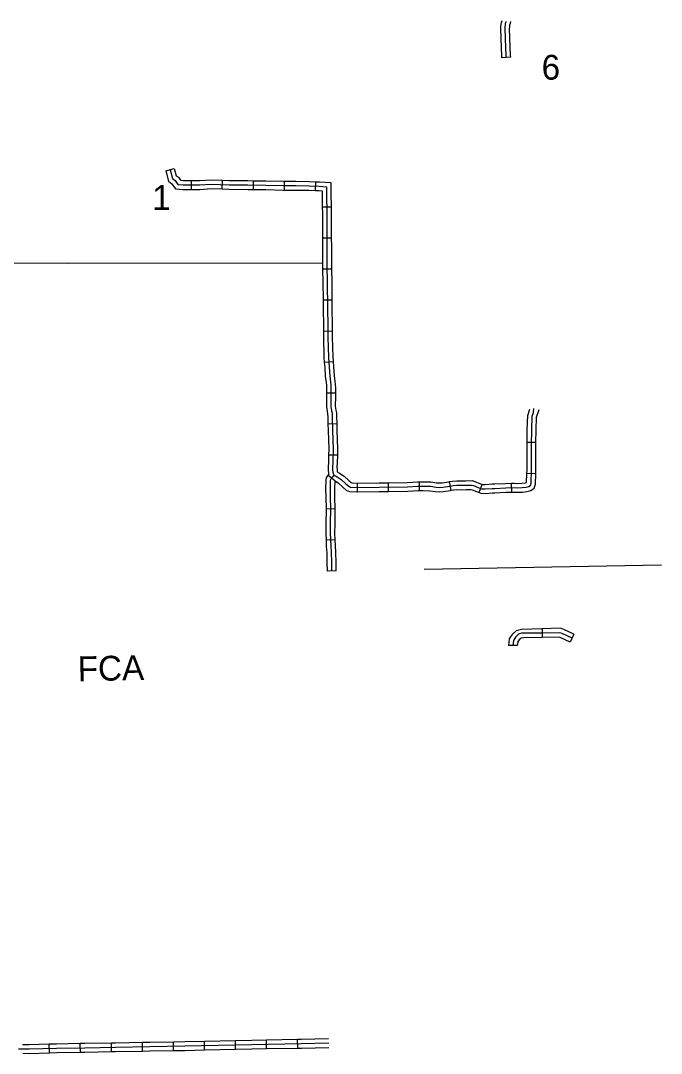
# Model space of a CAD drawing. Extents: x 1127717 to 1741049, y 2026793 to 2244711.
# Drawn here: x 1524221 to 1535120, y 2197760 to 2215332 of the extents above; entities that cross this region are included whole.
import ezdxf

# ---------------------------------------------------------------- set-up
doc = ezdxf.new("R2010")
doc.units = 0
for name, color, linetype in [('26', 7, 'Continuous'), ('32', 7, 'Continuous'), ('5', 7, 'Continuous')]:
    doc.layers.add(name, color=color, linetype=linetype)

msp = doc.modelspace()

# ---------------------------------------------------------------- linework, layer by layer
at = {"layer": '32'}
for p, q in [((1532558, 2214709), (1532408, 2214697)), ((1526689, 2212777), (1526834, 2212815)), ((1527126, 2212461), (1527126, 2212611)), ((1527651, 2212468), (1527656, 2212618)), ((1528181, 2212459), (1528183, 2212609)), ((1528710, 2212450), (1528710, 2212600)), ((1529235, 2212442), (1529240, 2212592)), ((1529352, 2212164), (1529502, 2212166)), ((1529356, 2211636), (1529506, 2211637)), ((1529358, 2211107), (1529508, 2211110)), ((1529366, 2210580), (1529516, 2210581)), ((1529373, 2210054), (1529523, 2210051)), ((1529387, 2209520), (1529537, 2209531)), ((1529425, 2208999), (1529575, 2208999)), ((1529448, 2208471), (1529598, 2208475)), ((1532987, 2208152), (1532837, 2208154)), ((1529460, 2207946), (1529610, 2207944)), ((1529568, 2207500), (1529451, 2207593)), ((1531007, 2207337), (1531007, 2207487)), ((1531547, 2207341), (1531516, 2207488)), ((1532983, 2207623), (1532833, 2207627)), ((1529953, 2207312), (1529950, 2207462)), ((1530480, 2207320), (1530479, 2207470)), ((1532022, 2207301), (1532073, 2207442)), ((1532575, 2207310), (1532573, 2207460)), ((1529572, 2207025), (1529422, 2207022)), ((1529572, 2206498), (1529422, 2206492)), ((1529589, 2205968), (1529439, 2205967)), ((1533091, 2204985), (1533094, 2204835)), ((1533632, 2204893), (1533570, 2204757)), ((1528934, 2197850), (1528931, 2198000)), ((1524712, 2197771), (1524707, 2197921)), ((1525238, 2197781), (1525236, 2197931)), ((1525766, 2197790), (1525764, 2197940)), ((1526294, 2197799), (1526292, 2197949)), ((1526822, 2197808), (1526820, 2197958)), ((1527350, 2197819), (1527347, 2197969)), ((1527878, 2197831), (1527875, 2197981)), ((1528406, 2197841), (1528403, 2197991))]:
    msp.add_line(p, q, dxfattribs=at)
for points in [[(1532408, 2214697), (1532405, 2214735), (1532399, 2214868), (1532393, 2215033), (1532389, 2215201), (1532391, 2215233)], [(1532391, 2215233), (1532400, 2215300), (1532412, 2215332)], [(1532483, 2214703), (1532480, 2214740), (1532474, 2214871), (1532468, 2215035), (1532464, 2215200), (1532468, 2215290), (1532486, 2215325)], [(1532558, 2214709), (1532555, 2214745), (1532549, 2214874), (1532543, 2215038), (1532539, 2215200), (1532540, 2215228)], [(1532540, 2215228), (1532544, 2215258), (1532552, 2215290), (1532561, 2215319)], [(1526689, 2212777), (1526737, 2212599), (1526795, 2212558), (1526854, 2212471), (1526981, 2212461), (1527126, 2212461)], [(1526762, 2212796), (1526802, 2212645), (1526849, 2212612), (1526896, 2212543), (1526984, 2212536), (1527264, 2212536), (1527464, 2212550), (1527766, 2212539), (1528086, 2212536), (1528392, 2212532), (1528690, 2212525), (1528894, 2212525), (1529127, 2212521), (1529298, 2212515), (1529423, 2212507)], [(1526834, 2212815), (1526867, 2212691), (1526904, 2212666), (1526938, 2212615), (1526987, 2212611), (1527126, 2212611)], [(1527126, 2212611), (1527261, 2212611), (1527463, 2212625), (1527656, 2212618)], [(1527656, 2212618), (1527768, 2212614), (1528087, 2212611), (1528183, 2212609)], [(1528183, 2212609), (1528393, 2212607), (1528691, 2212600), (1528710, 2212600)], [(1528710, 2212600), (1528894, 2212600), (1529129, 2212596), (1529240, 2212592)], [(1529240, 2212592), (1529302, 2212590), (1529498, 2212577), (1529499, 2212387), (1529502, 2212166)], [(1527126, 2212461), (1527267, 2212461), (1527465, 2212475), (1527651, 2212468)], [(1527651, 2212468), (1527764, 2212464), (1528086, 2212461), (1528181, 2212459)], [(1528181, 2212459), (1528391, 2212457), (1528690, 2212450), (1528710, 2212450)], [(1528710, 2212450), (1528893, 2212450), (1529125, 2212446), (1529235, 2212442)], [(1529235, 2212442), (1529295, 2212440), (1529349, 2212436), (1529349, 2212385), (1529352, 2212164)], [(1529423, 2212507), (1529424, 2212386), (1529428, 2212053), (1529430, 2211805), (1529432, 2211490), (1529432, 2211332), (1529432, 2211155), (1529438, 2210878), (1529442, 2210442), (1529448, 2210136), (1529448, 2210056), (1529446, 2209945), (1529456, 2209602), (1529468, 2209437), (1529478, 2209288), (1529492, 2209183), (1529498, 2209139), (1529500, 2209078), (1529500, 2208936), (1529498, 2208769), (1529510, 2208693), (1529518, 2208652), (1529520, 2208591), (1529526, 2208362), (1529536, 2208039), (1529532, 2207812), (1529526, 2207737), (1529528, 2207687), (1529532, 2207649), (1529551, 2207591)], [(1529352, 2212164), (1529353, 2212052), (1529355, 2211805), (1529356, 2211636)], [(1529502, 2212166), (1529503, 2212053), (1529505, 2211806), (1529506, 2211637)], [(1529356, 2211636), (1529357, 2211490), (1529357, 2211332), (1529357, 2211154), (1529358, 2211107)], [(1529506, 2211637), (1529507, 2211490), (1529507, 2211332), (1529507, 2211156), (1529508, 2211110)], [(1529358, 2211107), (1529363, 2210877), (1529366, 2210580)], [(1529508, 2211110), (1529513, 2210879), (1529516, 2210581)], [(1529366, 2210580), (1529367, 2210440), (1529373, 2210135), (1529373, 2210056), (1529373, 2210054)], [(1529516, 2210581), (1529517, 2210443), (1529523, 2210137), (1529523, 2210055), (1529523, 2210051)], [(1529373, 2210054), (1529371, 2209945), (1529381, 2209598), (1529387, 2209520)], [(1529523, 2210051), (1529521, 2209946), (1529531, 2209606), (1529537, 2209531)], [(1529387, 2209520), (1529393, 2209432), (1529404, 2209281), (1529418, 2209173), (1529424, 2209132), (1529425, 2209077), (1529425, 2208999)], [(1529537, 2209531), (1529543, 2209442), (1529553, 2209296), (1529567, 2209193), (1529573, 2209145), (1529575, 2209080), (1529575, 2208999)], [(1529425, 2208999), (1529425, 2208936), (1529423, 2208764), (1529437, 2208680), (1529443, 2208643), (1529445, 2208589), (1529448, 2208471)], [(1529575, 2208999), (1529575, 2208935), (1529573, 2208774), (1529584, 2208705), (1529593, 2208660), (1529595, 2208593), (1529598, 2208475)], [(1529514, 2205968), (1529513, 2206111), (1529509, 2206280), (1529501, 2206397), (1529492, 2206611), (1529494, 2206772), (1529497, 2207023), (1529492, 2207225), (1529490, 2207364), (1529494, 2207506), (1529497, 2207530), (1529512, 2207550), (1529533, 2207570), (1529551, 2207591), (1529576, 2207586), (1529608, 2207569), (1529675, 2207522), (1529754, 2207449), (1529801, 2207409), (1529834, 2207394), (1529942, 2207387), (1530320, 2207394), (1530799, 2207399), (1530978, 2207412), (1531063, 2207412), (1531191, 2207409), (1531289, 2207394), (1531345, 2207390), (1531401, 2207394), (1531520, 2207412), (1531578, 2207424), (1531640, 2207428), (1531718, 2207426), (1531796, 2207428), (1531891, 2207430), (1531925, 2207420), (1532004, 2207387), (1532063, 2207366), (1532125, 2207363), (1532243, 2207374), (1532289, 2207373), (1532472, 2207384), (1532615, 2207386), (1532679, 2207384), (1532752, 2207386), (1532820, 2207394), (1532866, 2207406), (1532892, 2207425), (1532903, 2207460), (1532910, 2207687), (1532911, 2208013), (1532911, 2208113), (1532915, 2208371), (1532921, 2208600), (1532944, 2208667), (1532949, 2208731)], [(1532837, 2208154), (1532840, 2208372), (1532847, 2208614), (1532883, 2208721)], [(1532987, 2208152), (1532990, 2208369), (1532996, 2208587), (1533041, 2208718)], [(1529448, 2208471), (1529451, 2208360), (1529461, 2208038), (1529460, 2207946)], [(1529598, 2208475), (1529601, 2208364), (1529611, 2208039), (1529610, 2207944)], [(1532833, 2207627), (1532835, 2207689), (1532836, 2208014), (1532836, 2208114), (1532837, 2208154)], [(1532983, 2207623), (1532985, 2207686), (1532986, 2208013), (1532986, 2208113), (1532987, 2208152)], [(1529460, 2207946), (1529457, 2207815), (1529451, 2207739), (1529453, 2207682), (1529458, 2207633), (1529465, 2207612)], [(1529610, 2207944), (1529607, 2207808), (1529601, 2207736), (1529603, 2207693), (1529607, 2207654)], [(1529422, 2207022), (1529417, 2207224), (1529415, 2207364), (1529419, 2207512), (1529425, 2207561), (1529465, 2207612)], [(1529572, 2207025), (1529567, 2207226), (1529565, 2207363), (1529569, 2207500), (1529569, 2207500), (1529568, 2207500)], [(1529568, 2207500), (1529572, 2207503), (1529628, 2207464), (1529704, 2207393), (1529760, 2207345), (1529816, 2207321), (1529941, 2207312), (1529953, 2207312)], [(1529607, 2207654), (1529647, 2207633), (1529723, 2207581), (1529804, 2207505), (1529841, 2207473), (1529853, 2207468), (1529944, 2207462), (1529950, 2207462)], [(1530479, 2207470), (1530795, 2207474), (1530975, 2207487), (1531007, 2207487)], [(1531007, 2207487), (1531064, 2207487), (1531198, 2207484), (1531297, 2207468), (1531344, 2207465), (1531392, 2207469), (1531507, 2207486), (1531516, 2207488)], [(1531516, 2207488), (1531568, 2207498), (1531639, 2207503), (1531718, 2207501), (1531794, 2207503), (1531901, 2207505), (1531950, 2207491), (1532031, 2207457), (1532073, 2207442)], [(1532573, 2207460), (1532615, 2207461), (1532679, 2207459), (1532747, 2207461), (1532806, 2207468), (1532829, 2207474), (1532833, 2207627)], [(1532575, 2207310), (1532614, 2207311), (1532679, 2207309), (1532758, 2207311), (1532833, 2207320), (1532898, 2207336), (1532955, 2207379), (1532978, 2207446), (1532983, 2207623)], [(1529950, 2207462), (1530319, 2207469), (1530479, 2207470)], [(1529953, 2207312), (1530321, 2207319), (1530480, 2207320)], [(1530480, 2207320), (1530802, 2207324), (1530981, 2207337), (1531007, 2207337)], [(1531007, 2207337), (1531062, 2207337), (1531184, 2207334), (1531280, 2207319), (1531346, 2207314), (1531409, 2207320), (1531533, 2207338), (1531547, 2207341)], [(1531547, 2207341), (1531589, 2207349), (1531641, 2207353), (1531719, 2207351), (1531798, 2207353), (1531881, 2207355), (1531900, 2207349), (1531977, 2207318), (1532022, 2207301)], [(1532073, 2207442), (1532078, 2207441), (1532123, 2207438), (1532241, 2207450), (1532288, 2207448), (1532470, 2207459), (1532573, 2207460)], [(1532022, 2207301), (1532048, 2207292), (1532127, 2207288), (1532245, 2207299), (1532290, 2207298), (1532475, 2207309), (1532575, 2207310)], [(1529422, 2206492), (1529417, 2206610), (1529419, 2206773), (1529422, 2207022), (1529422, 2207021)], [(1529572, 2206498), (1529567, 2206612), (1529569, 2206771), (1529572, 2207023), (1529572, 2207025)], [(1529439, 2205967), (1529438, 2206109), (1529434, 2206277), (1529426, 2206393), (1529422, 2206492)], [(1529589, 2205968), (1529588, 2206112), (1529584, 2206284), (1529576, 2206401), (1529572, 2206498)], [(1533091, 2204985), (1533089, 2204985), (1532740, 2204970), (1532648, 2204951), (1532582, 2204887), (1532551, 2204844)], [(1533601, 2204825), (1533431, 2204903), (1533392, 2204918), (1533090, 2204910), (1532742, 2204910), (1532688, 2204895), (1532641, 2204841), (1532603, 2204787), (1532594, 2204699)], [(1533632, 2204893), (1533460, 2204972), (1533405, 2204993), (1533091, 2204985)], [(1532551, 2204844), (1532530, 2204814), (1532519, 2204698)], [(1532676, 2204759), (1532670, 2204700), (1532519, 2204698)], [(1533094, 2204835), (1533091, 2204835), (1532777, 2204832), (1532736, 2204823), (1532701, 2204794), (1532674, 2204757)], [(1533570, 2204757), (1533401, 2204834), (1533378, 2204843), (1533094, 2204835)], [(1528403, 2197991), (1528931, 2198000)], [(1528931, 2198000), (1528993, 2198001), (1529459, 2198012)], [(1529459, 2198012), (1529460, 2198012)], [(1524182, 2197837), (1524207, 2197839), (1524367, 2197836), (1524833, 2197850), (1525313, 2197857), (1525834, 2197866), (1526419, 2197876), (1527016, 2197886), (1528153, 2197912), (1528995, 2197926), (1529461, 2197937)], [(1524254, 2197913), (1524367, 2197911), (1524707, 2197921)], [(1524707, 2197921), (1524832, 2197925), (1525236, 2197931)], [(1525236, 2197931), (1525312, 2197932), (1525764, 2197940)], [(1525764, 2197940), (1525833, 2197941), (1526292, 2197949)], [(1526292, 2197949), (1526418, 2197951), (1526820, 2197958)], [(1526820, 2197958), (1527014, 2197961), (1527347, 2197969)], [(1527347, 2197969), (1527875, 2197981)], [(1527350, 2197819), (1527878, 2197831)], [(1527875, 2197981), (1528152, 2197987), (1528403, 2197991)], [(1527878, 2197831), (1528155, 2197837), (1528406, 2197841)], [(1528406, 2197841), (1528934, 2197850)], [(1528934, 2197850), (1528996, 2197851), (1529462, 2197862)], [(1529462, 2197862), (1529463, 2197862)], [(1524259, 2197763), (1524367, 2197760), (1524712, 2197771)], [(1524712, 2197771), (1524835, 2197775), (1525238, 2197781)], [(1525238, 2197781), (1525314, 2197782), (1525766, 2197790)], [(1525766, 2197790), (1525836, 2197792), (1526294, 2197799)], [(1526294, 2197799), (1526421, 2197801), (1526822, 2197808)], [(1526822, 2197808), (1527017, 2197811), (1527350, 2197819)]]:
    msp.add_lwpolyline(points, dxfattribs=at)
at = {"layer": '5'}
for points in [[(1529357, 2211208), (1525021, 2211198), (1524110, 2211206)], [(1531084, 2205997), (1535120, 2206072)]]:
    msp.add_lwpolyline(points, dxfattribs=at)

# ---------------------------------------------------------------- texts
at = {"layer": '26'}
msp.add_text('FCA', height=422.4, rotation=1.2628, dxfattribs=at).set_placement((1525196, 2204090))
at = {"layer": '5'}
for s, p in [('6', (1533084, 2214328)), ('1', (1526460, 2212112))]:
    msp.add_text(s, height=422, dxfattribs=at).set_placement(p)

doc.saveas('drawing.dxf')
